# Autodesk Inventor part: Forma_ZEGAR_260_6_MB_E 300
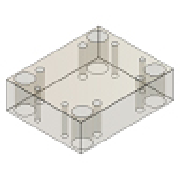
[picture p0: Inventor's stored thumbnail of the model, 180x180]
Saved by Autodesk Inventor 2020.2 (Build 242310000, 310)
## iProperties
IsCustomPart: 1
Manager: www.cadconsulting.pl
Company: Fabian Stasiak CAD Consulting
Created: 2014-02
Part Number: Forma_ZEGAR_260_6_MB_E 300
Material: S 55 C
Description: Support Plate
Document SubType Name: Modeling
Designer: F.Stasiak
Standard Revision: 1
Manufacturer: DME
Language: pl-PL
Size Designation: 496x346x36
Categories: <MemberInstance><Categories><Category DisplayName="Forma wtryskowa" InternalName="349578f2-f4d4-4954-8c09-8e99297a61c0" Mnemonic="MOLD"><Category DisplayName="P
Density: 7.85 g/cm^3
Appearance: Polycarbonate - Smoked
Catalog Web Link: www.expertbooks.pl
Author: F.Stasiak
Subject: Zbiór ćwiczeń. Autodesk Inventor 2020. Kurs Professional
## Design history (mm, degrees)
sketch "Sketch1"
  geometry: L1 (-173, 248)-(173, 248); L2 (173, 248)-(173, -248); L3 (173, -248)-(-173, -248); L4 (-173, -248)-(-173, 248); 6 further points
  constraints: 8 end point, 2 midpoint, 2 parallel, 1 horizontal, 1 horizontal alignment, 1 perpendicular, 1 vertical alignment
  dimensions: "d126" = 346 distance between parallel lines of L2 L4 (= W_); "d127" = 496 distance between parallel lines of L3 L1 (= L); "d128" = 95 horizontal distance of point (0, 0) point (-95, 233) (= 0.5 x RP_W); "d129" = 233 vertical distance of point (0, 0) point (-95, 233) (= 0.5 x RP_L); "d130" = 137 horizontal distance of point (0, 0) point (-137, 165) (= 0.5 x S1_W); "d131" = 165 vertical distance of point (0, 0) point (-137, 165) (= 0.5 x S1_L); "d132" = 208 vertical distance of point (0, 0) point (-137, 208) (= 0.5 x LS_L); "d133" = 137 horizontal distance of point (0, 0) point (-137, 208) (= 0.5 x LS_W)
extrude "Extrusion1" new body sketch "Sketch1" distance "d20" = 36 (= H_); taper "d30" = 0 deg
hole "Hole1" sketch "Sketch1" diameter "d134" = 42 (= LS_dt); stored, may be unused: countersink angle "d138" = 90 deg, drill point angle "d140" = 0 deg; dims "d135" = 6, "d136" = 4, "d137" = 2, "d139" = 36 (= H_)
pattern_linear "Rectangular Pattern1" dims "d163" = 416 (computed from LS_L, Nl), "d166" = 274 (computed from LS_W, Nw)
hole "Hole2" sketch "Sketch1" diameter "d141" = 18 (= S1_dt); stored, may be unused: countersink angle "d145" = 90 deg, drill point angle "d147" = 0 deg; dims "d142" = 6, "d143" = 4, "d144" = 2, "d146" = 36 (= H_)
pattern_linear "Rectangular Pattern2" dims "d157" = 330 (computed from S1_L, Ns), "d160" = 274 (computed from S1_W, Nw)
hole "Hole3" sketch "Sketch1" diameter "d148" = 14 (= RP_dt); stored, may be unused: countersink angle "d152" = 90 deg, drill point angle "d154" = 0 deg; dims "d149" = 6, "d150" = 4, "d151" = 2, "d153" = 36 (= H_)
pattern_linear "Rectangular Pattern3" dims "d169" = 466 (computed from RP_L, Nl), "d172" = 190 (computed from RP_W, Nw)
chamfer "Chamfer1" distance "d173" = 0.5; stored, may be unused: second distance "d174" = 2, angle "d175" = 45 deg
sketch "Szkic2"
  geometry: 1 further point
hole "Otwór12" sketch "Szkic2" at (0, 0) diameter "d176" = 4.5; stored, may be unused: countersink angle "d180" = 90 deg, drill point angle "d182" = 0 deg; dims "d177" = 6, "d178" = 4, "d179" = 2, "d181" = 8
sketch "Szkic3"
  geometry: 4 further points
hole "Otwór13" sketch "Szkic3" at (-54, 134), (-24, -134), (24, 134), (54, -134) diameter "d183" = 5; stored, may be unused: countersink angle "d187" = 90 deg, drill point angle "d189" = 0 deg; dims "d184" = 6, "d185" = 4, "d186" = 2, "d188" = 8
sketch "Szkic4"
  geometry: 4 further points
hole "Otwór14" sketch "Szkic4" at (-24, 134), (-54, -134), (54, 134), (24, -134) diameter "d190" = 5; stored, may be unused: countersink angle "d194" = 90 deg, drill point angle "d196" = 0 deg; dims "d191" = 6, "d192" = 4, "d193" = 2, "d195" = 8
sketch "Szkic5"
  geometry: 4 further points
hole "Otwór15" sketch "Szkic5" at (-54, 103.5), (-24, -103.5), (24, 103.5), (54, -103.5) diameter "d197" = 5; stored, may be unused: countersink angle "d201" = 90 deg, drill point angle "d203" = 0 deg; dims "d198" = 6, "d199" = 4, "d200" = 2, "d202" = 8
sketch "Szkic6"
  geometry: 4 further points
hole "Otwór16" sketch "Szkic6" at (-24, 103.5), (-54, -103.5), (54, 103.5), (24, -103.5) diameter "d204" = 5; stored, may be unused: countersink angle "d208" = 90 deg, drill point angle "d210" = 0 deg; dims "d205" = 6, "d206" = 4, "d207" = 2, "d209" = 8
sketch "Szkic7"
  geometry: 4 further points
hole "Otwór17" sketch "Szkic7" at (-47, 71.2), (-31, -71.2), (31, 71.2), (47, -71.2) diameter "d211" = 5; stored, may be unused: countersink angle "d215" = 90 deg, drill point angle "d217" = 0 deg; dims "d212" = 6, "d213" = 4, "d214" = 2, "d216" = 8
sketch "Szkic8"
  geometry: 4 further points
hole "Otwór18" sketch "Szkic8" at (-31, 71.2), (-47, -71.2), (47, 71.2), (31, -71.2) diameter "d218" = 5; stored, may be unused: countersink angle "d222" = 90 deg, drill point angle "d224" = 0 deg; dims "d219" = 6, "d220" = 4, "d221" = 2, "d223" = 8
sketch "Szkic9"
  geometry: 4 further points
hole "Otwór19" sketch "Szkic9" at (-48.5, 54), (-29.5, -54), (29.5, 54), (48.5, -54) diameter "d225" = 5; stored, may be unused: countersink angle "d229" = 90 deg, drill point angle "d231" = 0 deg; dims "d226" = 6, "d227" = 4, "d228" = 2, "d230" = 8
sketch "Szkic10"
  geometry: 4 further points
hole "Otwór20" sketch "Szkic10" at (-29.5, 54), (-48.5, -54), (48.5, 54), (29.5, -54) diameter "d232" = 5; stored, may be unused: countersink angle "d236" = 90 deg, drill point angle "d238" = 0 deg; dims "d233" = 6, "d234" = 4, "d235" = 2, "d237" = 8
sketch "Szkic11"
  geometry: 4 further points
hole "Otwór21" sketch "Szkic11" at (-57, 29), (-21, -29), (21, 29), (57, -29) diameter "d239" = 5; stored, may be unused: countersink angle "d243" = 90 deg, drill point angle "d245" = 0 deg; dims "d240" = 6, "d241" = 4, "d242" = 2, "d244" = 8
sketch "Szkic12"
  geometry: 4 further points
hole "Otwór22" sketch "Szkic12" at (-39, 35), (-39, -35), (39, 35), (39, -35) diameter "d246" = 5; stored, may be unused: countersink angle "d250" = 90 deg, drill point angle "d252" = 0 deg; dims "d247" = 6, "d248" = 4, "d249" = 2, "d251" = 8
sketch "Szkic13"
  geometry: 4 further points
hole "Otwór23" sketch "Szkic13" at (-21, 29), (-57, -29), (57, 29), (21, -29) diameter "d253" = 5; stored, may be unused: countersink angle "d257" = 90 deg, drill point angle "d259" = 0 deg; dims "d254" = 6, "d255" = 4, "d256" = 2, "d258" = 8
body "Solid1"
other parameters: "L" = 496 [user parameter; used in 1 equation term], "W_" = 346 [user parameter; used in 1 equation term], "H_" = 36 [user parameter; used in 4 equation terms], "LS_W" = 274 [user parameter; used in 2 equation terms], "LS_dt" = 42 [user parameter; used in 1 equation term], "S1_W" = 274 [user parameter; used in 2 equation terms], "RP_L" = 466 [user parameter; used in 2 equation terms], "RP_dt" = 14 [user parameter; used in 1 equation term], "LS_L" = 416 [user parameter; used in 2 equation terms], "S1_dt" = 18 [user parameter; used in 1 equation term]
